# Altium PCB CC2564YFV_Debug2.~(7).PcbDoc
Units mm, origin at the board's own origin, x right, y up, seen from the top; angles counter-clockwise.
Board outline 111.76 x 45.72 mm, 2 copper layers (Top Layer, Bottom Layer); 42 components, 48 nets, 258 pads, 1027 vias.
Unrouted connection lines stored in the file: 9.
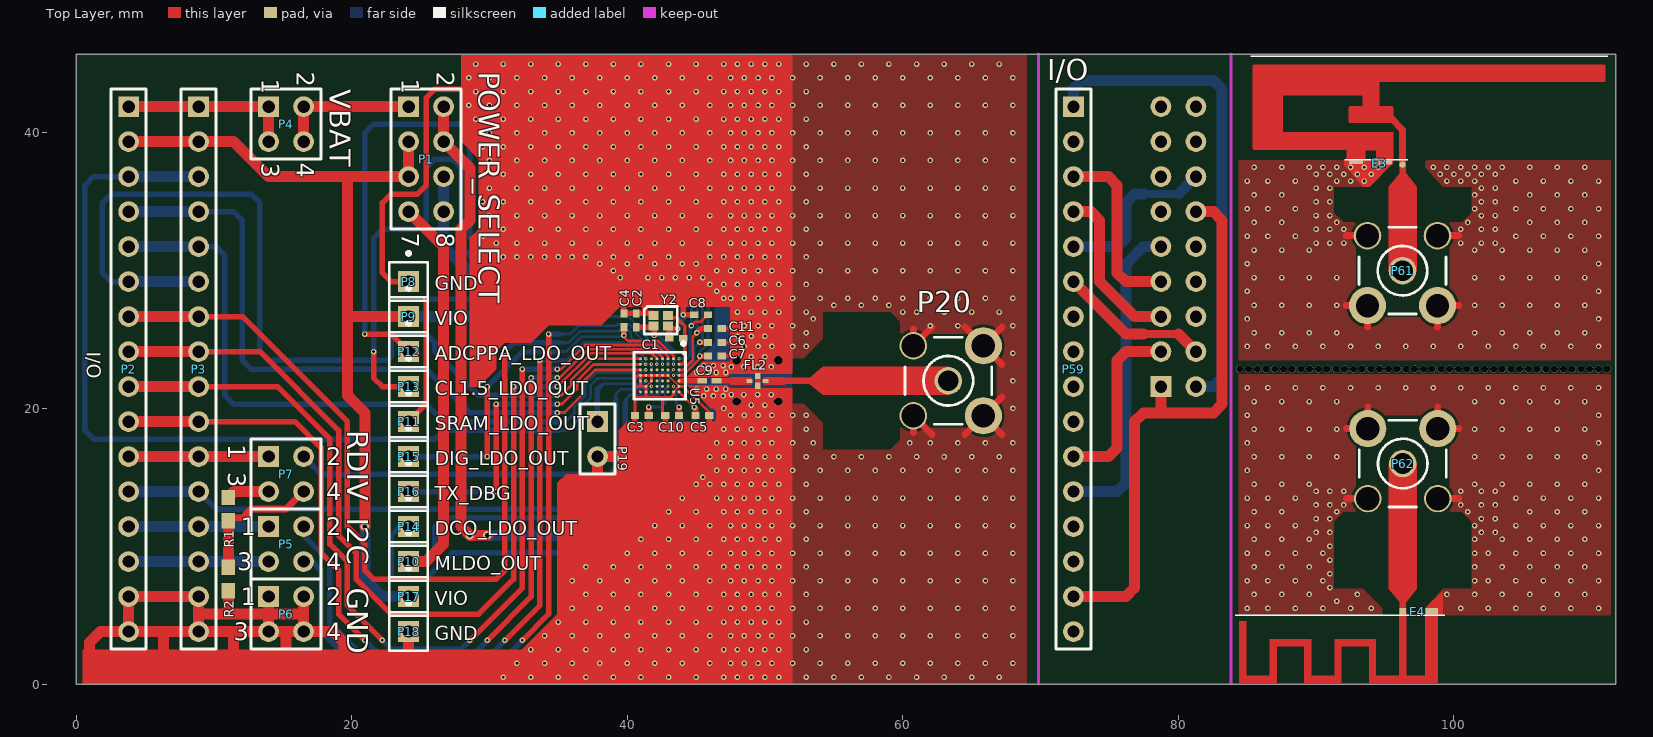
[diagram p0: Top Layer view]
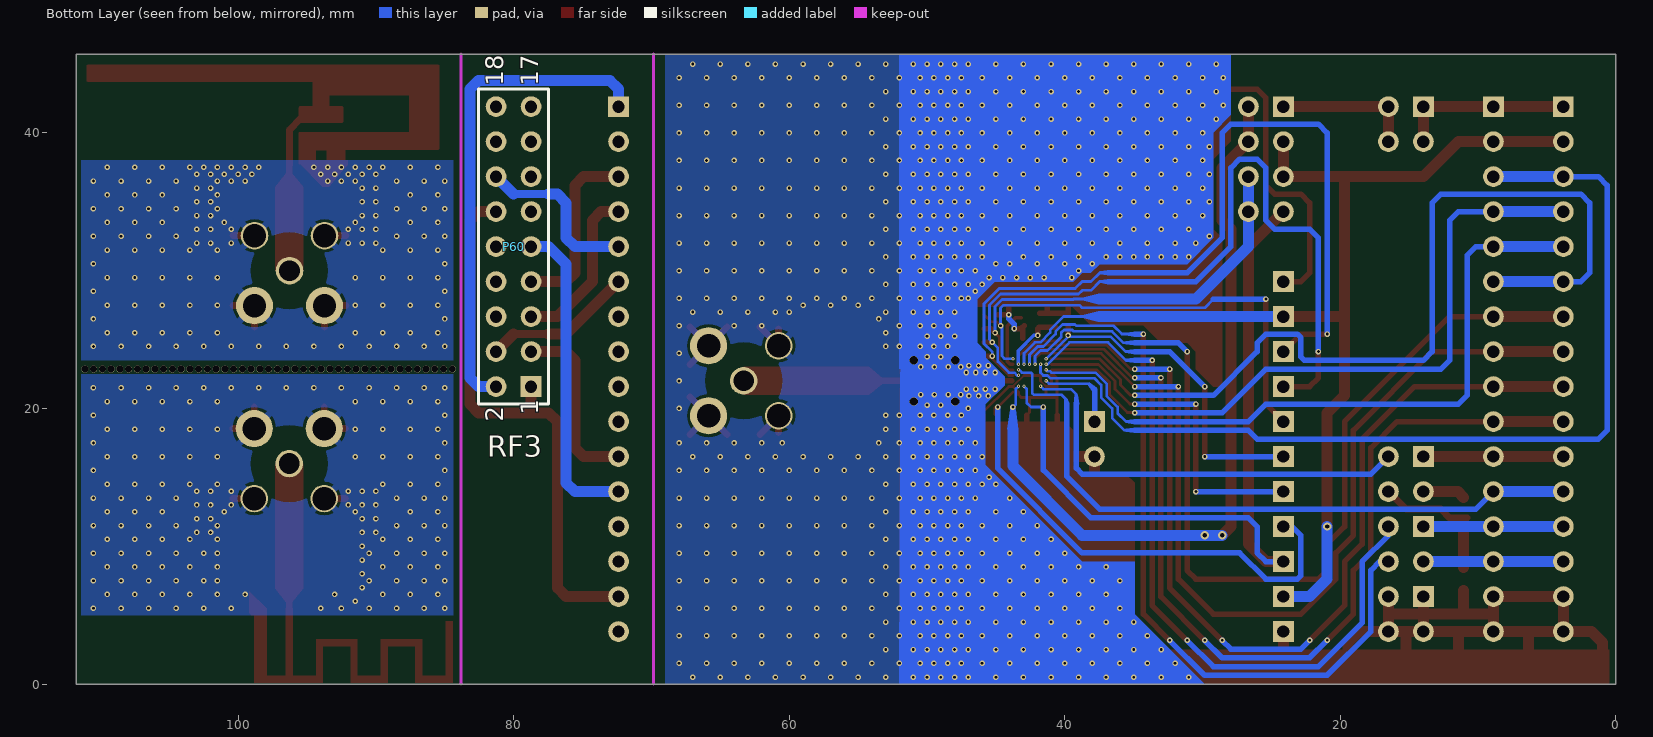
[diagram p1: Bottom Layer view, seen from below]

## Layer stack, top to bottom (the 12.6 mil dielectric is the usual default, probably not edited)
Top Solder: solder mask 0.0102, Solder Resist, Dk 3.5
Top Layer: signal copper 0.0356
Dielectric 1: dielectric 0.32, FR-4, Dk 4.8
Bottom Layer: signal copper 0.0356
Bottom Solder: solder mask 0.0102, Solder Resist, Dk 3.5

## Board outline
0,0 111.76,0 111.76,45.72 0,45.72

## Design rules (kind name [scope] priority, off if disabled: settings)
Clearance [All] p1: gap=0.1
ComponentClearance [All] p1 off: gap=0.1 collisioncheckmode=3 verticalgap=0.1 showdistances=FALSE
HoleSize [All] p1: absolutevalues=TRUE maxlimit=2.54 minlimit=0.1 maxpercent=80.000 minpercent=20.000
HoleToHoleClearance [All] p1: gap=0.1 allowstackedmicrovias=TRUE
MinimumSolderMaskSliver [All] p1: minsoldermaskwidth=0.1
PolygonConnect [All] p1: connectstyle=Relief reliefconductorwidth=0.5 reliefentries=4 polygonreliefangle="45 Angle" airgapwidth=0.2
RoutingVias [All] p1: holewidth=0.2 width=0.25 viastyle="Through Hole" minholewidth=0.1 minwidth=0.25 maxholewidth=0.2 maxwidth=0.45
SilkToSilkClearance [All] p1: silktosilkclearance=0.1
SilkToSolderMaskClearance [IsPad] p1 off: minsilkscreentomaskgap=0.1 clearancetoexposedcopper=TRUE
SolderMaskExpansion [All] p1: expansion=0.102
Width [All] p1: maxlimit=6 minlimit=0.1 preferedwidth=0.2
23 further rules are at their usual default settings.

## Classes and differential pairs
component class CC2564YFV_Debug2_RF: C1 C2 C3 C4 C5 C6 C7 C8 C9 C10 C11 FL2 P1 P2 P3 P4 P5 P6 P7 P8 P9 P10 P11 P12 P13 P14 P15 P16 P17 P18 P19 P20 R1 R2 U5 Y2
component class CC2564YFV_Debug2_Add: E3 E4 P59 P60 P61 P62

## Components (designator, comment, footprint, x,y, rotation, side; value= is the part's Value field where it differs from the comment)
C1 "Cap Semi 8 pF" 0402 43.56,25.1 r0 top
C2 "Cap Semi 8 pF" 0402 40.66,26.4 r270 top
C3 "C1005X5R1A105K050BB" 0402 41.06,19.5 r0 top
C4 "C1005X7R1H104M050BB" 0402 39.76,26.4 r270 top
C5 "C1005X7R1H104M050BB" 0402 45.46,19.5 r180 top
C6 "C1005X7R1H104M050BB" 0402 46.36,24.8 r180 top
C7 "C1005X7R1H104M050BB" 0402 46.36,23.8 r180 top
C8 "C1005X7R1H104M050BB" 0402 45.36,26.8 r0 top
C9 "GRM0335C1E220JA01D" 1-0201 45.96,22 r0 top
C10 "C1005X7R1H104M050BB" 0402 43.26,19.5 r0 top
C11 "C1005X5R1A105K050BB" 0402 46.36,25.8 r180 top
E3 "Inverted F Antenna" Inverted_F_Antenna 96.27,37.7 r0 top
E4 "Meandered IFA" Meandered_IFA 98.84,5 r180 top
FL2 "FI105L250014" FL105_Electrodes 49.46,22 r0 top
P1 "POWER_SELECT" HDR2X4 24.13,41.91 r270 top
P2 "I/O" HDR1X16 3.81,41.91 r270 top
P3 "I/O" HDR1X16 8.89,41.91 r270 top
P4 "VBAT" HDR2X2 13.97,41.91 r270 top
P5 "I2C" HDR2X2 13.97,11.43 r270 top
P6 "GND" HDR2X2 13.97,6.35 r270 top
P7 "RDIV" HDR2X2 13.97,16.51 r270 top
P8 "GND" PIN1 24.13,29.21 r0 top
P9 "VIO" PIN1 24.13,26.67 r0 top
P10 "MLDO_OUT" PIN1 24.13,8.89 r0 top
P11 "SRAM_LDO_OUT" PIN1 24.13,19.05 r0 top
P12 "ADCPPA_LDO_OUT" PIN1 24.13,24.13 r0 top
P13 "CL1.5_LDO_OUT" PIN1 24.13,21.59 r0 top
P14 "DCO_LDO_OUT" PIN1 24.13,11.43 r0 top
P15 "DIG_LDO_OUT" PIN1 24.13,16.51 r0 top
P16 "TX_DBG" PIN1 24.13,13.97 r0 top
P17 "VIO" PIN1 24.13,6.35 r0 top
P18 "GND" PIN1 24.13,3.81 r0 top
P19 "G5" HDR1X2 37.846,19.05 r270 top
P20 "SMA" SMA#1 63.31,22.01 r270 top
P59 "I/O" HDR1X16 72.39,41.91 r270 top
P60 "RF3" HDR2X9 78.74,21.59 r90 bottom
P61 "SMA" SMA#2 96.27,30 r0 top
P62 "SMA" SMA#1 96.29,16 r0 top
R1 "Res Chip 10 K" 3-0603 11.049,12.7 r90 top
R2 "Res Chip 12 K" 3-0603 11.049,7.62 r90 top
U5 "CC2564YFV" "YFV (R-XBGA-N54)" 42.36,22.2 r270 top
Y2 "NX1612AA-26MHZ-TI2" XTAL_QUAD_1.6x1.2mm 42.435,26.375 r180 top

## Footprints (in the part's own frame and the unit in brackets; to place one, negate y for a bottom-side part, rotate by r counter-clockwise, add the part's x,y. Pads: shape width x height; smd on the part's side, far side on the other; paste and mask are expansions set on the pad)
1-0201 [mm] "Chip Resistor; Body 0.6 x 0.3 mm (LxW typ)"
  rect 0.7x0.4 smd: 1(-0.525,0) 2(0.525,0)
3-0603 [mm] "Chip Resistor; Body 1.6 x 0.9 mm (LxW typ)"
  rect 1.1x1 smd: 1(-0.85,0) 2(0.85,0)
0402 [mm] "Chip Capacitor, Body 1.0x0.5mm, IPC High Density"
  rect 0.6x0.5 smd: 1(-0.5,0) 2(0.5,0)
  body extent -0.55,-0.3 0.55,0.3, height 1.3
FL105_Electrodes [mm]
  round 0.6 hole 0.6: 1(-1.5,1.5) 1(1.5,1.5) 3(-1.5,-1.5) 3(1.5,-1.5)
  rect 0.4x0.45 smd: 1(0,0.35) 3(0,-0.35)
  rect 0.45x0.3 smd: 2(0.575,0) 4(-0.575,0)
  Top Layer region: -0.2,-0.5 0.2,-0.5 0.2,0.5 -0.2,0.5
  Top Layer region: 0.5,-0.3 2,-0.3 2,0.3 0.5,0.3
  Top Layer region: -2,-0.3 -0.5,-0.3 -0.5,0.3 -2,0.3
  Top Layer region: -2,-2 2,-2 2,-0.5 -2,-0.5
  Top Layer region: -2,0.5 2,0.5 2,2 -2,2
  Top Layer region: -0.5,0.3 -0.425,0.15 -0.5,0.15
  Top Layer region: 0.425,0.15 0.5,0.3 0.5,0.15
  Top Layer region: -0.425,-0.15 -0.5,-0.3 -0.5,-0.15
  Top Layer region: 0.425,-0.15 0.5,-0.3 0.5,-0.15
HDR1X2 [mm] "Connector; Header; 2 Position"
  rect 1.5x1.5 hole 0.9: 1(0,0)
  round 1.5 hole 0.9: 2(2.54,0)
  silkscreen extent -1.27,-1.27 3.81,1.27
HDR1X16 [mm] "Connector; Header; 16 Position"
  rect 1.5x1.5 hole 0.9: 1(0,0)
  round 1.5 hole 0.9: 2(2.54,0) 3(5.08,0) 4(7.62,0) 5(10.16,0) 6(12.7,0) 7(15.24,0) 8(17.78,0) 9(20.32,0) 10(22.86,0) 11(25.4,0) 12(27.94,0) 13(30.48,0) 14(33.02,0) 15(35.56,0) 16(38.1,0)
  silkscreen extent -1.27,-1.27 39.37,1.27
HDR2X2 [mm] "Connector; Header; 2x2 Position"
  rect 1.5x1.5 hole 0.9: 1(0,0)
  round 1.5 hole 0.9: 2(0,2.54) 3(2.54,0) 4(2.54,2.54)
  silkscreen extent -1.27,-1.27 3.81,3.81
HDR2X4 [mm] "Connector; Header; 4x2 Position"
  rect 1.5x1.5 hole 0.9: 1(0,0)
  round 1.5 hole 0.9: 2(0,2.54) 3(2.54,0) 4(2.54,2.54) 5(5.08,0) 6(5.08,2.54) 7(7.62,0) 8(7.62,2.54)
  silkscreen extent -1.27,-1.27 8.89,3.81
HDR2X9 [mm] "Connector; Header; 9x2 Position"
  rect 1.5x1.5 hole 0.9: 1(0,0)
  round 1.5 hole 0.9: 2(0,2.54) 3(2.54,0) 4(2.54,2.54) 5(5.08,0) 6(5.08,2.54) 7(7.62,0) 8(7.62,2.54) 9(10.16,0) 10(10.16,2.54) 11(12.7,0) 12(12.7,2.54) 13(15.24,0) 14(15.24,2.54) 15(17.78,0) 16(17.78,2.54) 17(20.32,0) 18(20.32,2.54)
  silkscreen extent -1.27,-1.27 21.59,3.81
Inverted_F_Antenna [mm]
  round 0.46 smd mask+0: 1(0,0)
  rect 1x0.3 smd paste+0 mask+0: 2(-1.272,0.165) 3(-3.367,0.183)
  Top Layer region: -10.77,1.092 -10.237,1.092 -4.039,1.067 -4.039,0.127 -4.032,0.088 -4.009,0.055 -3.976,0.033 -3.937,0.025 -3.937,0.025 -2.788,0.025 -2.749,0.033 -2.716,0.055 -2.694,0.088 -2.686,0.127 -2.686,0.127 -2.686,1.025 -1.89,1.025 -1.89,0.127 -1.882,0.088 -1.86,0.055 -1.827,0.033 -1.788,0.025 -1.788,0.025 -0.788,0.025 -0.767,0.027 -0.747,0.033 -0.747,0.033 -0.702,0.051 -0.669,0.087 -0.658,0.135 -0.658,0.135 -0.658,0.135 -0.658,0.135 -0.658,0.135 -0.66,2.23 -0.67,2.274 -0.698,2.309 -0.698,2.309 -0.698,2.309 -0.721,2.338 -0.752,2.356 -0.788,2.363 -0.788,2.363 -8.686,2.363 -8.686,5.025 -2.89,5.025 -2.89,4.229 -3.788,4.229 -3.827,4.221 -3.86,4.199 -3.882,4.166 -3.89,4.127 -3.89,4.127 -3.89,3.127 -3.882,3.088 -3.86,3.055 -3.827,3.033 -3.788,3.025 -3.788,3.025 -0.83,3.025 -0.231,2.426 -0.231,0 -0.208,-0.1 -0.144,-0.18 -0.052,-0.225 0.051,-0.225 0.143,-0.18 0.207,-0.1 0.23,0 0.23,0 0.23,2.521 0.212,2.61 0.162,2.685 0.162,2.685 -0.686,3.533 -0.686,4.127 -0.694,4.166 -0.716,4.199 -0.749,4.221 -0.788,4.229 -0.788,4.229 -1.686,4.229 -1.686,6.025 14.63,6.025 14.669,6.033 14.702,6.055 14.724,6.088 14.732,6.127 14.732,6.127 14.732,7.137 14.724,7.176 14.702,7.21 14.669,7.232 14.63,7.239 14.63,7.239 -10.77,7.239 -10.809,7.232 -10.842,7.21 -10.864,7.176 -10.872,7.137 -10.872,7.137 -10.872,1.194 -10.864,1.155 -10.842,1.122 -10.809,1.1 -10.77,1.092
  silkscreen extent -11,0.34 14.9,7.86
Meandered_IFA [mm] "Meandered Inverted F Antenna"
  rect 0.5x0.5 smd mask+0: 1(2.55,-0.25)
  rect 0.9x0.5 smd mask+0: 2(0.45,-0.25)
  Top Layer region: 0,-0.5 0,4.89 5,4.89 5,2.25 7,2.25 7,4.89 9.7,4.89 9.7,2.25 11.7,2.25 11.7,4.89 14.4,4.89 14.4,0.45 13.9,0.45 13.9,4.39 12.2,4.39 12.2,1.75 9.2,1.75 9.2,4.39 7.5,4.39 7.5,1.75 4.5,1.75 4.5,4.39 2.8,4.39 2.8,-0.5 2.3,-0.5 2.3,4.39 0.9,4.39 0.9,-0.5
  silkscreen extent -0.5,0 14.7,0
PIN1 [mm] "Connector; Plug"
  rect 1.5x1.5 hole 0.9: 1(0,0)
  silkscreen extent -1.4,-1.4 1.4,2.17
SMA#1 [mm] "Connector; SMA Generic"
  round 2 hole 1.5: 1(0,0)
  round 2.7 hole 1.7: 2(-2.54,2.54) 2(2.54,2.54)
  round 2 hole 1.7: 2(-2.54,-2.54) 2(2.54,-2.54)
  silkscreen extent -3.15,-3.15 3.15,3.15
SMA#2 [mm] "Connector; SMA Generic"
  round 2 hole 1.5: 1(0,0)
  round 2.7 hole 1.7: 2(-2.54,-2.54) 2(2.54,-2.54)
  round 2 hole 1.7: 2(-2.54,2.54) 2(2.54,2.54)
  silkscreen extent -3.15,-3.15 3.15,3.15
XTAL_QUAD_1.6x1.2mm [mm]
  rect 0.75x0.65 smd: 1(-0.525,-0.375) 2(0.525,-0.375) 3(0.525,0.375) 4(-0.525,0.375)
  silkscreen extent -1.2,-1.02 1.2,0.98
"YFV (R-XBGA-N54)" [mm] "BGA, 54-Balls, Pitch 0.4mm"
  round 0.2 smd: A1(-1.4,1.4) A2(-1,1.4) A3(-0.6,1.4) A4(-0.2,1.4) A5(0.2,1.4) A6(0.6,1.4) A7(1,1.4) B1(-1.4,1) B2(-1,1) B3(-0.6,1) B4(-0.2,1) B6(0.6,1) B7(1,1) C1(-1.4,0.6) C2(-1,0.6) C3(-0.6,0.6) C4(-0.2,0.6) C5(0.2,0.6) C6(0.6,0.6) C7(1,0.6) D1(-1.4,0.2) D2(-1,0.2) D3(-0.6,0.2) D4(-0.2,0.2) D5(0.2,0.2) D6(0.6,0.2) D7(1,0.2) E1(-1.4,-0.2) E2(-1,-0.2) E3(-0.6,-0.2) E4(-0.2,-0.2) E5(0.2,-0.2) E6(0.6,-0.2) E7(1,-0.2) F1(-1.4,-0.6) F2(-1,-0.6) F3(-0.6,-0.6) F4(-0.2,-0.6) F5(0.2,-0.6) F6(0.6,-0.6) F7(1,-0.6) G1(-1.4,-1) G2(-1,-1) G3(-0.6,-1) G4(-0.2,-1) G5(0.2,-1) G6(0.6,-1) G7(1,-1) H1(-1.4,-1.4) H2(-1,-1.4) H3(-0.6,-1.4) H4(-0.2,-1.4) H5(0.2,-1.4) H7(1,-1.4)
  silkscreen extent -2.65,-1.88 1.52,1.88, body extent -1.91,-1.91 1.52,1.91, height 0.5

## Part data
C1 C2: "Chip Capacitor, 8 pF"
C3 C11: "1.0 uF/10 V 0402"
C4 C5 C6 C7 C8 C10: "0.1 uF/50 V 0402"
C9: "22 pF/25 V 0201"
E3: "Inverted F Antenna (Design Note DN0007; SWRU120B)"
E4: "Meandered Inverted F Antenna (Application Note AN043; SWRA117D)"
FL2: "2.4 GHz Low Pass Filter"
P1: library part "Header 4X2", "Header, 4-Pin, Dual row"
P2 P3 P59: library part "Header 16", "Header, 16-Pin"
P4 P5 P6 P7: library part "Header 2X2", "Header, 2-Pin, Dual row"
P8 P9 P10 P11 P12 P13 P14 P15 P16 P17 P18: library part Plug, "Plug"
P19: library part "Header 2", "Header, 2-Pin"
P20 P61 P62: "SMA Generic Connector"
P60: library part "Header 9X2", "Header, 9-Pin, Dual row"
R1: "Chip Resistor, 10 K"
R2: "Chip Resistor, 12 K"
U5: "CC2564, 54-balls DSBGA"
Y2: "Crystal Oscillator 26 MHz"

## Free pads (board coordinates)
  round 0.5 hole 0.5 unplated paste+0 mask+0: 0(84.455,22.86) 0(85.09,22.86) 0(85.725,22.86) 0(86.36,22.86) 0(86.995,22.86) 0(87.63,22.86) 0(88.265,22.86) 0(88.9,22.86) 0(89.535,22.86) 0(90.17,22.86) 0(90.805,22.86) 0(91.44,22.86) 0(92.075,22.86) 0(92.71,22.86) 0(93.345,22.86) 0(93.98,22.86) 0(94.615,22.86) 0(95.25,22.86) 0(95.885,22.86) 0(96.52,22.86) 0(97.155,22.86) 0(97.79,22.86) 0(98.425,22.86) 0(99.06,22.86) 0(99.695,22.86) 0(100.33,22.86) 0(100.965,22.86) 0(101.6,22.86) 0(102.235,22.86) 0(102.87,22.86) 0(103.505,22.86) 0(104.14,22.86) 0(104.775,22.86) 0(105.41,22.86) 0(106.045,22.86) 0(106.68,22.86) 0(107.315,22.86) 0(107.95,22.86) 0(108.585,22.86) 0(109.22,22.86) 0(109.855,22.86) 0(110.49,22.86) 0(111.125,22.86)

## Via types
v1: diameter 0.4, hole 0.2, Top Layer to Bottom Layer, tented both sides, 973 vias
v2: diameter 0.4, hole 0.2, Top Layer to Bottom Layer, 36 vias
v3: diameter 0.25, hole 0.1, Top Layer to Bottom Layer, 15 vias
v4: diameter 0.6, hole 0.3, Top Layer to Bottom Layer, 3 vias

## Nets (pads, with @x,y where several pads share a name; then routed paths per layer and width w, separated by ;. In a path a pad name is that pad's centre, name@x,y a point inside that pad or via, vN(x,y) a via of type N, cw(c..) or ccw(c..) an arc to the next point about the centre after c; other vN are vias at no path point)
ADCPPA_LDO_OUT: C7.2 P12.1 U5.A4 | length 60
  Top Layer w0.2: U5.A4 44.06,22.4 v2@45.26,23.6
  Top Layer w0.4: v2(20.955,25.4) 22.86,25.4 P12.1 ; v2(45.26,23.8) C7.2
  Bottom Layer w0.2: 36.83,29.845 37.465,29.845 38.1,29.21 38.735,29.21 39.245,28.7 44.76,28.7 45.86,27.6 45.86,24.7 45.26,24.1 v2(45.26,23.8)
  Bottom Layer w0.4: v2(20.955,25.4) 20.955,40.005 21.59,40.64 27.94,40.64 28.575,40.005 28.575,32.385 31.115,29.845 36.83,29.845
ANTENNA: FL2.2 P20.1 | length 4.6
  Top Layer w0.5: FL2.2@50.2,22.01 54.81,22.01
AUD_CLK: P2.8 P3.8 U5.E1 | length 68
  Top Layer w0.2: v2(34.925,21.59) 34.95,21.59 37.36,24 41.784,24 42.16,23.624 U5.E1
  Top Layer w0.4: P3.8 13.335,24.13 19.05,18.415 19.05,10.795 20.32,9.525 20.32,7.62 22.86,5.08 29.21,5.08 31.75,7.62 v2(31.75,21.59)
  Top Layer w0.8: P2.8 P3.8
  Bottom Layer w0.4: v2(31.75,21.59) v2(34.925,21.59)
AUD_FSYNC: P2.7 P3.7 U5.E2 | length 70.2
  Top Layer w0.4: P3.7 12.065,26.67 19.685,19.05 19.685,11.43 20.955,10.16 20.955,8.255 21.59,7.62 30.48,7.62 31.115,8.255 v2(31.115,24.13)
  Top Layer w0.8: P2.7 P3.7
  Bottom Layer w0.2: 34.925,24.765 35.725,24.765 36.56,25.6 39.36,25.6 39.46,25.7 40.06,25.7 40.26,25.5 40.26,25.2 41.26,24.2 41.76,24.2 42.16,23.8 v3(42.16,23.2)
  Bottom Layer w0.4: v2(31.115,24.13) 31.75,24.765 34.925,24.765
AUD_IN: P2.9 P3.9 U5.C1 | length 72.3
  Top Layer w0.2: v2(34.925,22.86) 35.22,22.86 36.96,24.6 42.136,24.6 42.96,23.776 U5.C1
  Top Layer w0.4: P3.9 14.605,21.59 18.415,17.78 18.415,10.16 19.685,8.89 19.685,5.715 v2(22.225,3.175) ; v2(28.575,3.175) 32.385,6.985 v2(32.385,22.86)
  Top Layer w0.8: P2.9 P3.9
  Bottom Layer w0.4: v2(22.225,3.175) 22.86,2.54 27.94,2.54 v2(28.575,3.175) ; v2(32.385,22.86) v2(34.925,22.86)
AUD_OUT: P2.10 P3.10 U5.D1 | length 71.1
  Top Layer w0.2: v2(34.925,22.225) 35.085,22.225 37.16,24.3 41.96,24.3 42.56,23.7 U5.D1
  Top Layer w0.4: P3.10 15.875,19.05 17.78,17.145 17.78,9.525 19.05,8.255 19.05,5.08 v2(20.955,3.175) ; v2(29.845,3.175) 33.02,6.35 v2(33.02,22.225)
  Top Layer w0.8: P2.10 P3.10
  Bottom Layer w0.4: v2(20.955,3.175) 22.225,1.905 28.575,1.905 v2(29.845,3.175) ; v2(33.02,22.225) v2(34.925,22.225)
BT_CTS: P2.6 P3.6 U5.H1 | length 68.1
  Top Layer w0.2: v2(34.925,20.955) 35.215,20.955 35.96,21.7 35.96,22.1 37.46,23.6 U5.H1
  Bottom Layer w0.4: P2.6 2.54,29.21 1.905,29.845 1.905,34.925 2.54,35.56 12.7,35.56 13.335,34.925 13.335,24.13 13.97,23.495 22.606,23.495 22.86,23.749 22.86,25.146 23.114,25.4 25.4,25.4 26.035,24.765 26.035,24.13 29.21,20.955 v2(34.925,20.955)
  Bottom Layer w0.8: P2.6 P3.6
BT_CTS_3: P59.6 P60.4 | length 11
  Top Layer w0.6: 77.47,25.4 80.01,25.4
  Top Layer w0.8: P59.6 76.2,25.4 77.47,25.4 ; 80.01,25.4 P60.4
BT_RTS: P2.5 P3.5 U5.G3 | length 51.1
  Bottom Layer w0.2: 34.925,19.05 35.56,19.05 36.16,19.65 36.16,20.1 36.96,20.9 36.96,21.8 37.76,22.6 40.96,22.6 41.06,22.7 41.26,22.7 v3(41.36,22.8)
  Bottom Layer w0.4: P3.5 10.16,31.75 10.795,31.115 10.795,20.955 11.43,20.32 25.4,20.32 26.67,19.05 34.925,19.05
  Bottom Layer w0.8: P2.5 P3.5
BT_RTS_3: P59.5 P60.14 | length 12.5
  Bottom Layer w0.6: 77.47,35.56 80.01,35.56
  Bottom Layer w0.8: P59.5 75.565,31.75 76.2,32.385 76.2,34.925 76.835,35.56 77.47,35.56 ; 80.01,35.56 P60.14
BT_RX: P2.4 P3.4 U5.H3 | length 50.8
  Top Layer w0.2: v2@35.06,19.7 35.46,19.7 36.76,21 36.76,21.9 37.66,22.8 U5.H3
  Bottom Layer w0.4: P3.4 11.43,34.29 12.065,33.655 12.065,23.495 12.7,22.86 25.4,22.86 28.575,19.685 v2(34.925,19.685)
  Bottom Layer w0.8: P2.4 P3.4
BT_RX_3: P59.4 P60.5 | length 12.1
  Top Layer w0.8: P59.4 73.66,34.29 74.295,33.655 74.295,29.21 76.835,26.67 P60.5
BT_SHUTD: P2.12 P3.12 U5.B3 | length 48.3
  Bottom Layer w0.2: 39.86,20.3 39.86,20.6 40.26,21 42.26,21 42.36,21.1 42.36,22.5 42.46,22.6 43.1,22.6 43.3,22.8 v3(43.36,22.8)
  Bottom Layer w0.4: P3.12 10.16,12.7 37.465,12.7 39.86,15.095 39.86,20.3
  Bottom Layer w0.8: P2.12 P3.12
BT_SHUTD_3: P59.12 P60.9 | length 23
  Bottom Layer w0.8: P59.12 75.565,13.97 76.2,14.605 76.2,30.48 77.47,31.75 P60.9
BT_TX: P2.3 P3.3 U5.F2 | length 70.6
  Bottom Layer w0.2: 34.925,18.415 35.675,18.415 36.56,19.3 36.56,20 37.36,20.8 37.36,21.7 37.86,22.2 41.06,22.2 41.26,22.4 41.56,22.4 41.76,22.6 v3(41.76,23.2)
  Bottom Layer w0.4: P2.3@3.175,36.83 1.27,36.83 0.635,36.195 0.635,18.415 1.27,17.78 26.035,17.78 26.67,18.415 34.925,18.415
  Bottom Layer w0.8: P2.3 P3.3
BT_TX_3: P59.3 P60.7 | length 13.2
  Top Layer w0.8: P59.3 74.93,36.83 75.565,36.195 75.565,29.845 76.2,29.21 P60.7
CL1.5_LDO_IN: C10.2 P1.2 P1.4 U5.B6 | length 57.5
  Top Layer w0.4: C10.2 v2(43.76,20.1)
  Top Layer w0.8: P1.2 P1.4 28.575,37.465 28.575,33.655 27.94,33.02 27.94,11.43 v4(28.575,10.795) v4(29.845,10.795)
  Bottom Layer w0.2: v3(43.36,21.6) 43.56,21.4 43.56,20.3 v2(43.76,20.1)
  Bottom Layer w0.4: 43.76,18.5 v2(43.76,20.1)
  Bottom Layer w0.8: v4(28.575,10.795) 38.735,10.795 43.76,15.82 43.76,18.5
CL1.5_LDO_OUT: C6.2 P13.1 U5.B4 | length 56
  Top Layer w0.4: v2(21.59,24.13) 21.59,22.225 22.225,21.59 P13.1 ; v2(45.26,24.8) C6.2
  Bottom Layer w0.2: 36.83,29.21 37.465,29.21 38.1,28.575 38.735,28.575 39.01,28.3 44.66,28.3 45.46,27.5 45.46,25 v2(45.26,24.8) 44.86,24.4 44.86,23.4 44.06,22.6 43.66,22.6 43.46,22.4 v3(43.36,22.4)
  Bottom Layer w0.4: v2(21.59,24.13) 21.59,32.385 22.225,33.02 24.765,33.02 25.4,33.655 25.4,37.465 26.035,38.1 27.305,38.1 27.94,37.465 27.94,31.75 30.48,29.21 36.83,29.21
DCO_LDO_OUT: C5.2 P14.1 U5.A7 | length 36.4
  Top Layer w0.2: U5.A7 v2@44.96,20
  Top Layer w0.4: C5.2@44.96,19.6 v2@44.96,20
  Bottom Layer w0.4: P14.1 23.495,11.43 22.86,10.795 22.86,7.874 23.114,7.62 25.4,7.62 27.305,9.525 38.735,9.525 44.86,15.65 v2(44.86,20.1)
DIG_LDO_OUT: C4.2 P15.1 U5.B1 U5.G1 | length 29.6
  Top Layer w0.2: v2@39.76,25.2 40.06,24.9 42.26,24.9 43.36,23.8 U5.B1
  Top Layer w0.4: v2(29.845,16.51) v2(29.845,21.59) ; v2(39.76,25.3) C4.2 C4.2@39.76,26
  Bottom Layer w0.2: 34.925,24.13 35.56,24.13 ; 35.59,24.13 36.66,25.2 v2@39.76,25.2 ; v2(39.76,25.3) v2@39.76,25.2 ; v3(41.36,23.6) v2@39.76,25.2
  Bottom Layer w0.4: P15.1 v2(29.845,16.51) ; v2(29.845,21.59) 32.385,24.13 34.925,24.13
GND: C1.1 C2.1 C3.1 C4.1 C5.1 C6.1 C7.1 C8.1 C10.1 C11.1 FL2.1 FL2.3 P2.15 P2.16 P3.15 P3.16 P6.1 P6.2 P6.3 P6.4 P8.1 P18.1 P19.2 P20.2 R2.1 U5.A6 U5.B7 U5.C4 U5.D4 U5.E4 U5.F4 U5.F5 U5.G4 U5.G6 U5.G7 U5.H4 U5.H5 Y2.2 Y2.4 | length 123.7
  Top Layer w0.1: U5.C4 U5.A6
  Top Layer w0.11: 41.46,21.7 41.66,21.9 ; 43.46,21.3 43.66,21.5
  Top Layer w0.15: U5.G6 41.46,21.7 ; 41.66,21.9 U5.F5
  Top Layer w0.18: U5.B7 43.46,21.3 ; 43.66,21.5 U5.A6
  Top Layer w0.2: C3.1 40.56,20.8 ; 40.96,21.6 U5.H5 U5.H4 ; U5.F5 U5.F4 ; C10.1@42.56,19.7 42.56,20.8 ; U5.C4 U5.D4 U5.E4 U5.F4 ; U5.B7 43.36,21 43.16,20.8 42.56,20.8 ; U5.A6 44.06,21.6 45.96,19.7 C5.1 ; 40.56,20.8 41.36,20.8 ; 40.56,20.8 40.56,21.6 ; 40.56,21.6 U5.G6 U5.G7 41.36,20.8 ; 40.56,21.6 40.56,22.2 40.76,22.4 U5.H4 ; U5.H4 U5.G4 U5.F4 ; 41.36,20.8 42.56,20.8
  Top Layer w0.3: C7.1 47.76,23.8 ; C6.1 47.66,24.8 ; C11.1 47.76,25.8
  Top Layer w0.4: P8.1 22.86,29.21 22.225,29.845 22.225,34.925 22.86,35.56 24.765,35.56 25.4,36.195 25.4,42.545 26.035,43.18 29.845,43.18 ; 39.76,27.5 C4.1 Y2.2@41.81,26.9 ; 40.56,18.495 C3.1 ; 41.26,26.9 41.26,27.5 ; 42.76,18.495 C10.1 ; Y2.4 Y2.4@43.06,25.9 ; C1.1 Y2.4@43.06,25.9 ; v2(43.66,25.8) 43.16,25.8 Y2.4@43.06,25.9 ; 44.06,27.5 v2(44.06,26.8) C8.1 ; 45.96,18.495 C5.1
  Top Layer w0.5: 60.77,18.26 60.77,19.47 62.12,18.12 ; 60.77,25.76 60.77,24.55 v1@62.12,25.9 ; 64.5,18.12 P20.2@65.85,19.47 ; 64.5,25.9 P20.2@65.85,24.55 ; 67.2,18.12 P20.2@65.85,19.47 ; 67.2,20.82 P20.2@65.85,19.47 ; 67.2,23.2 P20.2@65.85,24.55 ; 67.2,25.9 P20.2@65.85,24.55
  Top Layer w0.8: 0.96,2.5 0.96,3 1.77,3.81 P2.16 ; 6.35,2.54 6.35,3.81 ; 11.049,5.461 R2.1 ; 11.43,2.54 11.43,3.81 ; P6.1 13.97,5.08 ; 15.24,2.54 15.24,3.81 ; P6.2 16.51,5.08 ; 19.46,2.5 19.46,3 18.65,3.81 P6.4 ; 24.13,2.54 P18.1 ; 37.846,14.224 P19.2 39.37,16.51 ; P2.16 6.35,3.81 ; P2.16 P2.15 P3.15 8.89,5.08 ; 6.35,3.81 P3.16 ; P3.16 11.43,3.81 ; P3.16 8.89,5.08 ; 8.89,5.08 13.97,5.08 ; 11.43,3.81 P6.3 ; P6.3 15.24,3.81 ; P6.3 13.97,5.08 ; 13.97,5.08 16.51,5.08 ; 15.24,3.81 P6.4 ; P6.4 16.51,5.08
  Bottom Layer w0.4: v2(43.66,25.8) 43.66,26.1 44.06,26.5 v2(44.06,26.8)
  other v1: 31,0.5 33,0.5 35,0.5 37,0.5 39,0.5 41,0.5 43,0.5 45,0.5 47,0.5 48,0.5 49,0.5 50,0.5 51,0.5 32,1.5 34,1.5 36,1.5 38,1.5 40,1.5 42,1.5 44,1.5 46,1.5 47.5,1.5 48.5,1.5 49.5,1.5 50.5,1.5 52,1.5 33,2.5 35,2.5 37,2.5 39,2.5 41,2.5 43,2.5 45,2.5 47,2.5 48,2.5 49,2.5 50,2.5 51,2.5 34,3.5 36,3.5 38,3.5 40,3.5 42,3.5 44,3.5 46,3.5 47.5,3.5 48.5,3.5 49.5,3.5 50.5,3.5 52,3.5 35,4.5 37,4.5 39,4.5 41,4.5 43,4.5 45,4.5 47,4.5 48,4.5 49,4.5 50,4.5 51,4.5 36,5.5 38,5.5 40,5.5 42,5.5 44,5.5 46,5.5 47.5,5.5 48.5,5.5 49.5,5.5 50.5,5.5 52,5.5 37,6.5 39,6.5 41,6.5 43,6.5 45,6.5 47,6.5 48,6.5 49,6.5 50,6.5 51,6.5 36,7.5 38,7.5 40,7.5 42,7.5 44,7.5 46,7.5 47.5,7.5 48.5,7.5 49.5,7.5 50.5,7.5 52,7.5 37,8.5 39,8.5 41,8.5 43,8.5 45,8.5 47,8.5 48,8.5 49,8.5 50,8.5 51,8.5 40,9.5 42,9.5 44,9.5 46,9.5 47.5,9.5 48.5,9.5 49.5,9.5 50.5,9.5 52,9.5 41,10.5 43,10.5 45,10.5 47,10.5 48,10.5 49,10.5 50,10.5 51,10.5 42,11.5 44,11.5 46,11.5 47.5,11.5 48.5,11.5 49.5,11.5 50.5,11.5 52,11.5 43,12.5 45,12.5 47,12.5 48,12.5 49,12.5 50,12.5 51,12.5 44,13.5 46.5,13.5 47.5,13.5 48.5,13.5 49.5,13.5 50.5,13.5 52,13.5 45,14.5 46,14.5 47,14.5 48,14.5 49,14.5 50,14.5 51,14.5 45.5,15 46.5,15.5 47.5,15.5 48.5,15.5 49.5,15.5 50.5,15.5 52,15.5 46,16.5 47,16.5 48,16.5 49,16.5 50,16.5 51,16.5 46.5,17.5 47.5,17.5 48.5,17.5 49.5,17.5 50.5,17.5 52,17.5 47,18.5 48,18.5 49,18.5 50,18.5 51,18.5 47.5,19.5 48.5,19.5 49.5,19.5 50.5,19.5 52,19.5 47,20 49,20.25 50,20.25 45.56,20.91 46.26,20.91 46.96,20.91 47.56,21.01 48.46,21.01 49.46,21.01 50.46,21.01 45.06,21.41 45.76,21.41 46.46,21.41 47.16,21.41 45.06,22.61 45.76,22.61 46.46,22.61 47.16,22.61 47.56,23.01 48.46,23.01 49.46,23.01 50.46,23.01 45.56,23.11 46.26,23.11 46.96,23.11 49,23.75 50,23.75 48.5,24.5 49.5,24.5 50.5,24.5 52,24.5 48,25.25 49,25.25 50,25.25 48.5,26 49.5,26 50.5,26 52,26 62,26 48,27 49,27 50,27 51,27 47,28 47.5,28 48.5,28 49.5,28 50.5,28 52,28 46.5,28.5 46,29 47,29 48,29 49,29 50,29 51,29 39.5,29.5 41.5,29.5 42.5,29.5 43.5,29.5 44.5,29.5 45.5,29.5 39,30 46.5,30 47.5,30 48.5,30 49.5,30 50.5,30 52,30 38,30.5 40,30.5 42,30.5 44,30.5 45,30.5 31,31 32,31 33,31 34,31 35,31 36,31 37,31 39,31 41,31 43,31 46,31 47,31 48,31 49,31 50,31 51,31 30.5,32 32,32 34,32 36,32 38,32 40,32 42,32 44,32 46,32 47.5,32 48.5,32 49.5,32 50.5,32 52,32 29.5,32.5 31,33 33,33 35,33 37,33 39,33 41,33 43,33 45,33 47,33 48,33 49,33 50,33 51,33 30,34 32,34 34,34 36,34 38,34 40,34 42,34 44,34 46,34 47.5,34 48.5,34 49.5,34 50.5,34 52,34 29.5,35 31,35 33,35 35,35 37,35 39,35 41,35 43,35 45,35 47,35 48,35 49,35 50,35 51,35 30,36 32,36 34,36 36,36 38,36 40,36 42,36 44,36 46,36 47.5,36 48.5,36 49.5,36 50.5,36 52,36 29.5,37 31,37 33,37 35,37 37,37 39,37 41,37 43,37 45,37 47,37 48,37 49,37 50,37 51,37 30,38 32,38 34,38 36,38 38,38 40,38 42,38 44,38 46,38 47.5,38 48.5,38 49.5,38 50.5,38 52,38 29.5,39 31,39 33,39 35,39 37,39 39,39 41,39 43,39 45,39 47,39 48,39 49,39 50,39 51,39 30,40 32,40 34,40 36,40 38,40 40,40 42,40 44,40 46,40 47.5,40 48.5,40 49.5,40 50.5,40 52,40 29,41 31,41 33,41 35,41 37,41 39,41 41,41 43,41 45,41 47,41 48,41 49,41 50,41 51,41 28.5,42 30,42 32,42 34,42 36,42 38,42 40,42 42,42 44,42 46,42 47.5,42 48.5,42 49.5,42 50.5,42 52,42 29,43 31,43 33,43 35,43 37,43 39,43 41,43 43,43 45,43 47,43 48,43 49,43 50,43 51,43 28.5,44 30,44 32,44 34,44 36,44 38,44 40,44 42,44 44,44 46,44 47.5,44 48.5,44 49.5,44 50.5,44 52,44 29,45 31,45 33,45 35,45 37,45 39,45 41,45 43,45 45,45 47,45 48,45 49,45 50,45 51,45
GND_3: P59.15 P59.16 P60.1 P60.12 | length 41.1
  Top Layer w0.8: P59.15 76.2,6.35 76.835,6.985 76.835,19.05 77.47,19.685 78.74,19.685 ; P60.1 78.74,19.685 ; P60.12 82.55,34.29 83.185,33.655 83.185,20.32 82.55,19.685 78.74,19.685
I2C_SCL: P5.2 U5.G2 | length 52.9
  Top Layer w0.4: v2(31.115,3.175) 33.655,5.715 v2(33.655,23.495)
  Bottom Layer w0.2: 34.925,23.495 35.56,23.495 36.865,24.8 39.66,24.8 41.26,23.2 v3(41.36,23.2)
  Bottom Layer w0.4: P5.2 16.51,10.795 18.415,8.89 18.415,4.445 21.59,1.27 29.21,1.27 v2(31.115,3.175) ; v2(33.655,23.495) 34.925,23.495
I2C_SDA: P5.4 U5.D2 | length 56.3
  Top Layer w0.4: v2(32.385,3.175) 34.29,5.08 v2(34.29,25.4)
  Bottom Layer w0.2: 34.925,25.4 35.86,25.4 36.46,26 39.16,26 39.26,26.1 40.16,26.1 40.66,25.6 40.66,25.4 41.56,24.5 41.96,24.5 42.56,23.9 v3(42.56,23.2)
  Bottom Layer w0.4: P5.4 17.145,8.89 17.78,8.255 17.78,3.81 20.955,0.635 29.845,0.635 v2(32.385,3.175) ; v2(34.29,25.4) 34.925,25.4
MLDO_IN: C11.2 P1.6 P1.8 U5.A3 | length 31.5
  Top Layer w0.2: U5.A3 44.036,22.8 44.76,23.524 44.76,25.2 v2(45.06,25.5)
  Top Layer w0.4: v2(45.06,25.5) 45.36,25.8 C11.2
  Bottom Layer w0.2: 37.465,27.94 39.37,27.94 ; 39.37,27.9 44.56,27.9 45.06,27.4 v2(45.06,25.5)
  Bottom Layer w0.8: P1.6 26.67,31.75 30.48,27.94 37.465,27.94
MLDO_OUT: C3.2 P1.7 P10.1 U5.C6 | length 57.3
  Top Layer w0.4: C3.2 v2(41.56,20.1)
  Top Layer w0.8: P10.1 25.4,8.89 26.67,10.16 26.67,31.75 P1.7
  Bottom Layer w0.2: v2(41.56,20.1) 42.46,20.1 42.76,20.4 42.76,21.4 v3(42.96,21.6)
  Bottom Layer w0.4: P10.1 25.4,8.89 26.035,9.525 26.035,11.43 26.67,12.065 38.1,12.065 41.56,15.525 v2(41.56,20.1)
NetE3_1: E3.1 P61.1 | length 2.2
  Top Layer w0.5: 96.29,35.5 E3.1@96.29,37.75
NetE3_2: E3.2 E3.3 P61.2 | length 9.3
  Top Layer w0.5: 92.173,27.46 93.73,27.46 93.73,25.903 ; 92.173,32.54 P61.2@93.73,32.54 ; 98.81,25.903 98.81,27.46 100.368,27.46 ; P61.2@98.81,32.54 100.368,32.54
  other v1: 93.5,36.5 93,37 94,37 92.5,37.5 93.5,37.5 94.5,37.5
NetE4_1: E4.1 P62.1 | length 2.2
  Top Layer w0.5: E4.1 96.29,7.5
NetE4_2: E4.2 P62.2 | length 9.3
  Top Layer w0.5: 92.193,13.46 P62.2@93.75,13.46 ; 92.193,18.54 93.75,18.54 93.75,20.098 ; P62.2@98.83,13.46 100.388,13.46 ; 98.83,20.098 98.83,18.54 100.388,18.54
NetP7_3: P7.3 R1.2 | length 3.1
  Top Layer w0.8: R1.2 11.469,13.97 P7.3
NetP7_4: P7.4 R1.1 R2.2 | length 9.9
  Top Layer w0.5: R1.1@10.795,12.065 12.065,12.065 12.7,12.7 15.24,12.7 P7.4
  Top Layer w0.8: R2.2 R1.1
NetP19_1: P19.1 U5.G5 | length 6.1
  Bottom Layer w0.2: 37.815,21.355 38.26,21.8 41.16,21.8 v3(41.36,22)
  Bottom Layer w0.4: P19.1@37.815,19.055 37.815,21.355
P2_1: P2.1 P3.1 P4.1 P4.3 | length 12.7
  Top Layer w0.8: P2.1 P3.1 P4.1 P4.3
P2_11: P2.11 P3.11 P7.1 | length 10.2
  Top Layer w0.8: P2.11 P3.11 P7.1
P2_13: P2.13 P3.13 P5.1 | length 10.2
  Bottom Layer w0.8: P2.13 P3.13 P5.1
P2_14: P2.14 P3.14 P5.3 | length 10.2
  Bottom Layer w0.8: P2.14 P3.14 P5.3
RF: C9.2 FL2.4 | length 2.4
  Top Layer w0.4: C9.2 FL2.4
RF_IO: C9.1 U5.A5 | length 1.6
  Top Layer w0.4: 43.86,22 C9.1
SLOW_CLK: P7.2 U5.F6 | length 31.5
  Bottom Layer w0.2: 39.16,20.3 39.16,21 39.56,21.4 41.56,21.4 v3(41.76,21.6)
  Bottom Layer w0.4: P7.2 17.78,15.24 38.735,15.24 39.16,15.665 39.16,20.3
SLOW_CLK_3: P59.11 P60.3 | length 13.2
  Top Layer w0.8: P59.11 74.93,16.51 75.565,17.145 75.565,23.495 76.2,24.13 P60.3
SRAM_LDO_OUT: C8.2 P11.1 U5.A1 | length 35.1
  Top Layer w0.2: v2(44.66,26) 44.96,26.3 45.36,26.3 C8.2
  Top Layer w0.4: P11.1 25.4,20.32 v2(25.4,27.94)
  Bottom Layer w0.2: 29.21,27.94 29.845,27.305 38.735,27.305 38.93,27.5 44.46,27.5 44.66,27.3 v2(44.66,26) 44.56,25.9 44.56,23.8 44.36,23.6 v3(43.76,23.6)
  Bottom Layer w0.4: v2(25.4,27.94) 29.21,27.94
TX_DBG: P16.1 U5.H2 | length 24.7
  Top Layer w0.2: v2(34.925,20.32) 35.28,20.32 36.36,21.4 36.36,22 37.56,23.2 U5.H2
  Top Layer w0.4: v2(30.48,13.97) v2(30.48,20.32)
  Bottom Layer w0.4: P16.1 v2(30.48,13.97) ; v2(30.48,20.32) v2(34.925,20.32)
VBAT: P1.1 P4.2 P4.4 | length 10.2
  Top Layer w0.8: P4.4 P4.2 P1.1
VBAT_3: P59.1 P60.2 | length 35.7
  Bottom Layer w0.8: P59.1 72.39,43.18 73.025,43.815 82.55,43.815 83.185,43.18 83.185,22.225 82.55,21.59 P60.2
VIO: P1.3 P1.5 P2.2 P3.2 P9.1 P17.1 U5.C2 | length 82.7
  Top Layer w0.8: P2.2 P3.2 11.43,39.37 13.97,36.83 P1.5 P1.3 ; 19.685,26.67 P9.1 ; 19.685,36.83 19.685,20.955 20.955,19.685 v4(20.955,11.43)
  Bottom Layer w0.2: 37.465,26.6 37.484,26.619 ; 37.465,26.67 40.09,26.67 41.06,25.7 41.06,25.5 41.76,24.8 42.16,24.8 42.96,24 v3(42.96,23.2)
  Bottom Layer w0.8: v4(20.955,11.43) 20.955,7.62 22.225,6.35 P17.1 ; P9.1 37.465,26.67
XTAL_M: C2.2 U5.B2 Y2.3 | length 4.7
  Top Layer w0.4: C2.2 41.86,25.9 41.96,25.8 v2(41.96,25.3)
  Bottom Layer w0.254: v2(41.96,25.3) 42.26,25.3 43.36,24.2 v3(43.36,23.2)
XTAL_P: C1.2 U5.A2 Y2.1 | length 4.3
  Top Layer w0.254: Y2.1@43.16,26.6 43.56,26.6 44.16,26 44.16,23.387 43.973,23.2 U5.A2
pads on no net: P59.2 P59.7 P59.8 P59.9 P59.10 P59.13 P59.14 P60.6 P60.8 P60.10 P60.11 P60.13 P60.15 P60.16 P60.17 P60.18 U5.C3 U5.C5 U5.C7 U5.D3 U5.D5 U5.D6 U5.D7 U5.E3 U5.E5 U5.E6 U5.E7 U5.F1 U5.F3 U5.F7 U5.H7
copper on no net:
  other v1: 53,0.5 55,0.5 57,0.5 59,0.5 61,0.5 63,0.5 65,0.5 67,0.5 54,1.5 56,1.5 58,1.5 60,1.5 62,1.5 64,1.5 66,1.5 68,1.5 53,2.5 54,3.5 56,3.5 58,3.5 60,3.5 62,3.5 64,3.5 66,3.5 68,3.5 53,4.5 54,5.5 56,5.5 58,5.5 60,5.5 62,5.5 64,5.5 66,5.5 68,5.5 85,5.5 86.5,5.5 88.5,5.5 90.5,5.5 92.5,5.5 94,5.5 100.5,5.5 102.5,5.5 104.5,5.5 106.5,5.5 108.5,5.5 110.5,5.5 91.5,6 53,6.5 85.5,6.5 87.5,6.5 89.5,6.5 93,6.5 99.5,6.5 101.5,6.5 103.5,6.5 105.5,6.5 107.5,6.5 109.5,6.5 91,7 54,7.5 56,7.5 58,7.5 60,7.5 62,7.5 64,7.5 66,7.5 68,7.5 85,7.5 86.5,7.5 88.5,7.5 90.5,7.5 101.5,7.5 102.5,7.5 104.5,7.5 106.5,7.5 108.5,7.5 110.5,7.5 91,8 53,8.5 85.5,8.5 87.5,8.5 89.5,8.5 101.5,8.5 103.5,8.5 105.5,8.5 107.5,8.5 109.5,8.5 91,9 54,9.5 56,9.5 58,9.5 60,9.5 62,9.5 64,9.5 66,9.5 68,9.5 85,9.5 86.5,9.5 88.5,9.5 90.5,9.5 101.5,9.5 102.5,9.5 104.5,9.5 106.5,9.5 108.5,9.5 110.5,9.5 91,10 53,10.5 85.5,10.5 87.5,10.5 89.5,10.5 101.5,10.5 103.5,10.5 105.5,10.5 107.5,10.5 109.5,10.5 90,11 91,11 102,11 103,11 54,11.5 56,11.5 58,11.5 60,11.5 62,11.5 64,11.5 66,11.5 68,11.5 85,11.5 86.5,11.5 88.5,11.5 101.5,11.5 104.5,11.5 106.5,11.5 108.5,11.5 110.5,11.5 90,12 91,12 102,12 103,12 53,12.5 85.5,12.5 87.5,12.5 91.5,12.5 101,12.5 105.5,12.5 107.5,12.5 109.5,12.5 90,13 91,13 92,13 100.5,13 102,13 103,13 54,13.5 56,13.5 58,13.5 60,13.5 62,13.5 64,13.5 66,13.5 68,13.5 85,13.5 86.5,13.5 88.5,13.5 104.5,13.5 106.5,13.5 108.5,13.5 110.5,13.5 90,14 91,14 92,14 100.5,14 102,14 103,14 53,14.5 85.5,14.5 87.5,14.5 89.5,14.5 101.5,14.5 103.5,14.5 105.5,14.5 107.5,14.5 109.5,14.5 54,15.5 56,15.5 58,15.5 60,15.5 62,15.5 64,15.5 66,15.5 68,15.5 85,15.5 110.5,15.5 53,16.5 55,16.5 57,16.5 59,16.5 61,16.5 63,16.5 65,16.5 67,16.5 85.5,16.5 87.5,16.5 89.5,16.5 91.5,16.5 101.5,16.5 103.5,16.5 105.5,16.5 107.5,16.5 109.5,16.5 53.5,17.5 60.5,17.5 62,17.5 64,17.5 66,17.5 68,17.5 85,17.5 110.5,17.5 53,18.5 85.5,18.5 87.5,18.5 89.5,18.5 91.5,18.5 101.5,18.5 103.5,18.5 105.5,18.5 107.5,18.5 109.5,18.5 53,19.5 85,19.5 110.5,19.5 68,20 85.5,20.5 87.5,20.5 89.5,20.5 91.5,20.5 101.5,20.5 103.5,20.5 105.5,20.5 107.5,20.5 109.5,20.5 85,21.5 86.5,21.5 88.5,21.5 90.5,21.5 92.5,21.5 94.5,21.5 96.5,21.5 98.5,21.5 100.5,21.5 102.5,21.5 104.5,21.5 106.5,21.5 108.5,21.5 110.5,21.5 68,22 68,24 53,24.5 85,24.5 86.5,24.5 88.5,24.5 90.5,24.5 92.5,24.5 94.5,24.5 96.5,24.5 98.5,24.5 100.5,24.5 102.5,24.5 104.5,24.5 106.5,24.5 108.5,24.5 110.5,24.5 53,25.5 85.5,25.5 87.5,25.5 89.5,25.5 91.5,25.5 101.5,25.5 103.5,25.5 105.5,25.5 107.5,25.5 109.5,25.5 64,26 68,26 53.5,26.5 85,26.5 110.5,26.5 53,27 60,27 61,27 63,27 65,27 67,27 55,27.5 57,27.5 59,27.5 85.5,27.5 87.5,27.5 89.5,27.5 91.5,27.5 101.5,27.5 103.5,27.5 105.5,27.5 107.5,27.5 109.5,27.5 54,28 56,28 58,28 60,28 62,28 64,28 66,28 68,28 85,28.5 110.5,28.5 53,29 85.5,29.5 87.5,29.5 89.5,29.5 91.5,29.5 101.5,29.5 103.5,29.5 105.5,29.5 107.5,29.5 109.5,29.5 54,30 56,30 58,30 60,30 62,30 64,30 66,30 68,30 85,30.5 110.5,30.5 53,31 85.5,31.5 87.5,31.5 89.5,31.5 101.5,31.5 103.5,31.5 105.5,31.5 107.5,31.5 109.5,31.5 54,32 56,32 58,32 60,32 62,32 64,32 66,32 68,32 90,32 91,32 92,32 100.5,32 102,32 103,32 85,32.5 86.5,32.5 88.5,32.5 104.5,32.5 106.5,32.5 108.5,32.5 110.5,32.5 53,33 90,33 91,33 92,33 100.5,33 102,33 103,33 85.5,33.5 87.5,33.5 91.5,33.5 101,33.5 105.5,33.5 107.5,33.5 109.5,33.5 54,34 56,34 58,34 60,34 62,34 64,34 66,34 68,34 90,34 91,34 102,34 103,34 85,34.5 86.5,34.5 88.5,34.5 101.5,34.5 104.5,34.5 106.5,34.5 108.5,34.5 110.5,34.5 53,35 90,35 91,35 102,35 103,35 85.5,35.5 87.5,35.5 101.5,35.5 105.5,35.5 107.5,35.5 109.5,35.5 54,36 56,36 58,36 60,36 62,36 64,36 66,36 68,36 90,36 91,36 102,36 103,36 85,36.5 86.5,36.5 88.5,36.5 91.5,36.5 92.5,36.5 99.5,36.5 100.5,36.5 101.5,36.5 104.5,36.5 106.5,36.5 108.5,36.5 110.5,36.5 53,37 90,37 91,37 92,37 99,37 100,37 101,37 102,37 103,37 85.5,37.5 87.5,37.5 89.5,37.5 90.5,37.5 91.5,37.5 98.5,37.5 99.5,37.5 100.5,37.5 101.5,37.5 102.5,37.5 103.5,37.5 105.5,37.5 107.5,37.5 109.5,37.5 54,38 56,38 58,38 60,38 62,38 64,38 66,38 68,38 53,39 54,40 56,40 58,40 60,40 62,40 64,40 66,40 68,40 53,41 54,42 56,42 58,42 60,42 62,42 64,42 66,42 68,42 53,43 54,44 56,44 58,44 60,44 62,44 64,44 66,44 68,44 53,45 55,45 57,45 59,45 61,45 63,45 65,45 67,45

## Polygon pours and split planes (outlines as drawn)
GND on Bottom Layer "Bottom Layer-No Net" (solid, pour order 10): 69,45.7 51.7,45.7 51.7,0 69,0
NetE3_2 on Bottom Layer "Bottom Layer-No Net" (solid, pour order 8): 84.39,23.5 84.39,38 111.39,38 111.39,23.5
NetE4_2 on Bottom Layer "Bottom Layer-No Net" (solid, pour order 9): 84.39,22.5 84.39,5 111.39,5 111.39,22.5
GND on Top Layer "Bottom Layer-No Net" (solid, pour order 8): 51.76,45.7 51.76,0 69,0 69,45.7
NetE3_2 on Top Layer "Bottom Layer-No Net" (solid, pour order 11): 84.39,23.5 111.39,23.5 111.39,38 84.39,38
NetE4_2 on Top Layer "Bottom Layer-No Net" (solid, pour order 12): 84.39,22.5 111.39,22.5 111.39,5 84.39,5

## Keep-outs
Keep-Out Layer:
  lines w0.2: 69.85,0 69.85,45.72 ; 83.82,0 83.82,45.72

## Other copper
Top Layer:
  rectangle net GND: 47.46,0 52,21.5
  rectangle net GND: 0.46,0 47.5,2.5
  rectangle net GND: 47.46,22.5 52,45.7
  region: 97.945,5 97.945,5.495 97.94,5.5 99.19,6.75 99.19,5.15 99.04,5
  region net ANTENNA: 63.31,23.01 63.31,21.01 54.21,21.01 53.21,21.81 53.21,22.21 54.21,23.01
  pour cut-out: 66.81,25.41 66.81,18.61 59.81,18.61 59.807,17.716 59.096,17.01 54.21,17.01 54.21,18.96 52.81,20.36 51.5,20.36 51.5,23.66 52.81,23.66 54.21,25.06 54.21,27.01 59.096,27.01 59.807,26.301 59.81,25.41
  region net GND: 47.46,22.5 47.26,22.3 44.36,22.3 45.46,23.4 47.46,23.4
  region net NetE3_2: 93.39,36.1 93.89,36.1 95.612,37.835 95.59,38 92.025,38 92.025,37.665 92.29,37.4
  region net NetE3_1: 95.29,30 97.29,30 97.29,36.1 96.49,37.1 96.09,37.1 95.29,36.1
  pour cut-out: 92.89,26.7 99.69,26.6 99.69,33.5 100.59,33.5 101.29,34.2 101.29,36.1 99.19,36.1 97.94,37.5 97.94,38.2 95.49,38.2 93.39,36.1 91.29,36.1 91.29,34.2 91.99,33.5 92.89,33.5
  pour cut-out: 92.89,19.5 99.69,19.5 99.69,12.5 100.584,12.497 101.29,11.786 101.29,6.9 99.19,6.9 97.94,5.5 97.94,4.8 94.79,4.8 94.79,5.5 93.39,6.9 91.29,6.9 91.29,11.786 91.999,12.497 92.89,12.5
  region net NetE4_1: 95.29,16 97.29,16 97.29,6.9 96.49,5.9 96.09,5.9 95.29,6.9
  region net GND: 32.36,2.5 34.925,5.08 34.925,14.605 35.56,15.24 38.735,15.24 39.37,15.875 39.37,18.415 40.005,19.05 46.355,19.05 46.46,19.2 46.46,19.8 46.26,20 46.06,20 44.36,21.7 47.26,21.7 47.46,21.5 47.46,2.5
  region net GND: 47.86,27.4 39.46,27.4 38.1,26.035 34.29,26.035 33.02,24.765 31.115,24.765 30.48,24.13 30.48,22.86 29.21,21.59 28.575,21.59 28.575,32.385 29.21,33.02 29.21,38.1 27.96,39.4 27.96,45.7 47.86,45.7
Bottom Layer:
  region net I2C_SDA: 35.56,25.502 35.001,25.578 35.001,25.222 35.56,25.298
  region net AUD_FSYNC: 35.56,24.867 35.001,24.943 35.001,24.587 35.56,24.663
  region net DIG_LDO_OUT: 35.56,24.232 35.001,24.308 35.001,23.952 35.56,24.028
  region net I2C_SCL: 35.56,23.597 35.001,23.673 35.001,23.317 35.56,23.393
  region net BT_RTS: 35.56,19.152 35.001,19.228 35.001,18.872 35.56,18.948
  region net BT_TX: 35.56,18.517 35.001,18.593 35.001,18.237 35.56,18.313
  region net NetP19_1: 37.694,21.514 38.227,21.895 38.329,21.717 37.998,21.26
  region net SLOW_CLK: 38.964,20.32 39.065,21.006 39.268,20.98 39.345,20.32
  region net BT_SHUTD: 39.675,20.371 39.776,20.65 40.03,20.625 40.056,20.32
  region net CL1.5_LDO_IN: 43.36,18.5 43.56,19.9 43.96,19.9 44.16,18.5
  region net MLDO_IN: 38.735,28.042 37.567,28.321 37.592,27.559 38.735,27.838
  region net VIO: 38.735,26.772 37.567,27.051 37.592,26.289 38.735,26.568
  region net ADCPPA_LDO_OUT: 36.906,30.023 37.465,29.947 37.44,29.743 36.906,29.667
  region net CL1.5_LDO_OUT: 36.906,29.388 37.465,29.312 37.44,29.108 36.906,29.032
  region net GND: 27.96,45.7 27.96,41.3 29.21,40.005 29.21,32.385 31.115,30.48 37.465,30.48 38.1,29.845 38.735,29.845 39.37,29.21 45.085,29.21 46.355,27.94 46.355,24.765 45.72,24.13 45.72,22.86 52,22.9 52,45.7
  region net GND: 29.845,0 34.925,5.08 34.925,8.89 38.735,8.89 45.76,15.9 45.76,20.3 44.36,21.7 44.36,22.3 45.76,23.7 51.26,23.7 51.26,27.2 51.9,27.2 52,0
  pour cut-out: 63.31,24.796 ccw(c63.31,22.01) 60.524,22.01 ccw(c63.31,22.01) 63.31,19.224 ccw(c63.31,22.01) 66.096,22.01 ccw(c63.31,22.01)
  pour cut-out: 93.504,30 cw(c96.29,30) 96.29,32.786 cw(c96.29,30) 99.076,30 cw(c96.29,30) 96.29,27.214 cw(c96.29,30)
  pour cut-out: 93.504,16 ccw(c96.29,16) 96.29,13.214 ccw(c96.29,16) 99.076,16 ccw(c96.29,16) 96.29,18.786 ccw(c96.29,16)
